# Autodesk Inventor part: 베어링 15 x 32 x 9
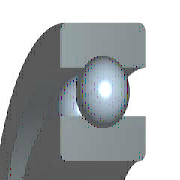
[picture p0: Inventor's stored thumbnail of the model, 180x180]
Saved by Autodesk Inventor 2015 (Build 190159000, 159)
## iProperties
IsCustomPart: 0
Created: 2012-02
Part Number: 베어링 15 x 32 x 9
Material: 강철, 연강
Description: 깊은 그루브 볼 베어링
Document SubType Name: Modeling
Standard: KS B 2023
Designer: mduedu
Standards Organization: KS
Language: ko-KR
Size Designation: 6002 - 15 x 32 x 9
Categories: <MemberInstance><Categories><Category DisplayName="샤프트 부품" InternalName="7f7aeb1f-a693-4053-b835-cee3144e0d98" Mnemonic="SHFT"><Category DisplayName="베어링" Inter
Density: 1 g/cm^3
Appearance: 노란색
Author: mduedu
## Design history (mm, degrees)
sketch "스케치" dims "d0" = 4.42 (= -0.26 x WD + 0.26 x BD)
  geometry: L1 (2.29, 11.75)-(6.71, 11.75); L2 (4.5, 11.75)-(4.5, 9.54); L3 (4.5, 11.75)-(4.5, 13.96); L4 (2.858, 10.271)-(0, 10.271); L5 (0, 7.5)-(9, 7.5); L6 (2.858, 13.229)-(0, 13.229); L7 (0, 16)-(9, 16); L8 (9, 7.5)-(9, 10.271); L9 (6.142, 10.271)-(9, 10.271); L10 (6.142, 13.229)-(9, 13.229); L11 (9, 16)-(9, 13.229); L12 (-1.4, 0)-(8.4, 0) reference; L13 (0, -0.3)-(0, 5.3) reference
  constraints: 22 end point, 4 point on line, 2 collinear, 2 perpendicular, 2 symmetric about line, 1 midpoint, 1 parallel, 14 other
  dimensions: "d9" = 15 diameter of L5 L12 (= WD); "d11" = 32 diameter of L7 L12 (= BD); "d12" = 9 distance between parallel lines of L8 L13 (= KB); "d13" = 20.542 diameter of L9 L12 (= 0.326 x BD + 0.674 x WD)
revolve "본체" stored, may be unused: angle "d6" = 90 deg
revolve "볼" stored, may be unused: angle "d7" = 90 deg
pattern_circular "IDS_ARRAYBALL[SIMPL:T]" dims angle "d3" = 360 deg
body "Solid1"
fillet "모깎기1" dims "d1" = 0.3 (= KRS)
other parameters: "WD" = 15 [user parameter; used in 5 equation terms], "BD" = 32 [user parameter; used in 5 equation terms], "KB" = 9 [user parameter; used in 1 equation term], "KRS" = 0.3 [user parameter; used in 1 equation term], "d4" = 0, "d5" = 0, "d8" = 0, "d14" = 0, "d15" = 0, "BBA" = 0 [user parameter], "BC0" = 2850000 [user parameter], "BC" = 5590000 [user parameter], "BR" = 16 (= 0.5 x BD) [user parameter], "WR" = 7.5 (= 0.5 x WD) [user parameter]
